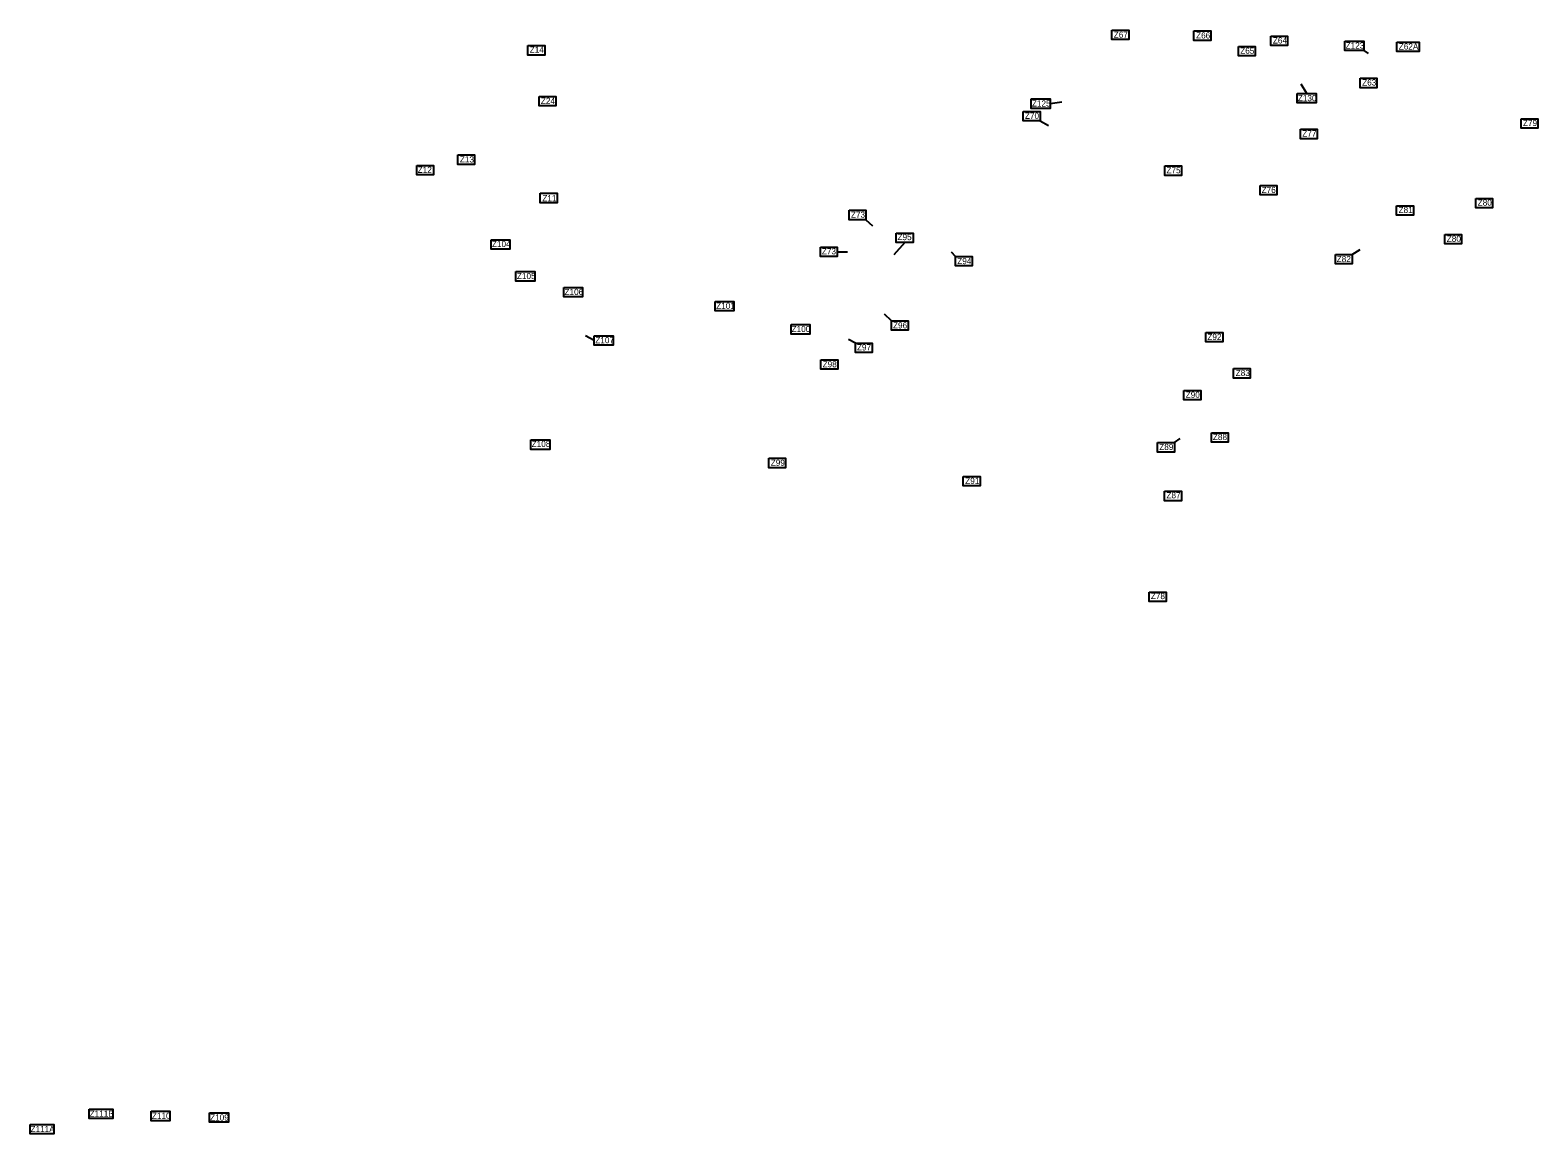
# Model space of a CAD drawing. Extents: x -443483 to -437761, y -1135258 to -1129797.
# Drawn here: x -443483 to -441026, y -1133472 to -1131673 of the extents above; entities that cross this region are included whole.
import ezdxf

# ---------------------------------------------------------------- set-up
doc = ezdxf.new("R2010")
doc.units = 0
doc.layers.add('Vrstva 3', color=7, linetype='Continuous')
doc.layers.add('Vrstva 8', color=7, linetype='Continuous')

msp = doc.modelspace()

# ---------------------------------------------------------------- linework, layer by layer
at = {"layer": 'Vrstva 3'}
for p, q in [((-441837, -1131820.4), (-441823.1, -1131827.9)), ((-442121, -1131981.6), (-442110, -1131991.6)), ((-442167.8, -1132033.9), (-442150.7, -1132034.1)), ((-442057.7, -1132018.8), (-442075.2, -1132039)), ((-441975.1, -1132041.6), (-441981.4, -1132034.6)), ((-441328.2, -1132038.3), (-441315, -1132030.3)), ((-442079.2, -1132146.3), (-442090.7, -1132135.7)), ((-442563.8, -1132178.3), (-442578.2, -1132171.1)), ((-442137.9, -1132182.9), (-442149.2, -1132176.8)), ((-441618.1, -1132344.9), (-441608.8, -1132338.2))]:
    msp.add_line(p, q, dxfattribs=at)
for points in [[(-441719.9, -1131672.7), (-441692.5, -1131672.7), (-441692.5, -1131688.1), (-441719.9, -1131688.1)], [(-441586.1, -1131673.9), (-441558.7, -1131673.9), (-441558.7, -1131689.3), (-441586.1, -1131689.3)], [(-441460.9, -1131682.5), (-441433.5, -1131682.5), (-441433.5, -1131697.9), (-441460.9, -1131697.9)], [(-441255.7, -1131692.3), (-441219.3, -1131692.3), (-441219.3, -1131707.7), (-441255.7, -1131707.7)], [(-442671.7, -1131697.8), (-442644.4, -1131697.8), (-442644.4, -1131713.2), (-442671.7, -1131713.2)], [(-441513.5, -1131699.1), (-441486.1, -1131699.1), (-441486.1, -1131714.5), (-441513.5, -1131714.5)], [(-441315.3, -1131751.1), (-441287.9, -1131751.1), (-441287.9, -1131766.5), (-441315.3, -1131766.5)], [(-442653.5, -1131780.7), (-442626.2, -1131780.7), (-442626.2, -1131796.1), (-442653.5, -1131796.1)], [(-441864.3, -1131805), (-441837, -1131805), (-441837, -1131820.4), (-441864.3, -1131820.4)], [(-441412.5, -1131834.2), (-441385.1, -1131834.2), (-441385.1, -1131849.6), (-441412.5, -1131849.6)], [(-441053, -1131817.2), (-441025.6, -1131817.2), (-441025.6, -1131832.6), (-441053, -1131832.6)], [(-442786.3, -1131876), (-442759, -1131876), (-442759, -1131891.4), (-442786.3, -1131891.4)], [(-442853.1, -1131893), (-442825.7, -1131893), (-442825.7, -1131908.4), (-442853.1, -1131908.4)], [(-441633.7, -1131893.9), (-441606.4, -1131893.9), (-441606.4, -1131909.3), (-441633.7, -1131909.3)], [(-442651.8, -1131938.6), (-442624.4, -1131938.6), (-442624.4, -1131954), (-442651.8, -1131954)], [(-441478.3, -1131925.9), (-441450.9, -1131925.9), (-441450.9, -1131941.3), (-441478.3, -1131941.3)], [(-441255.9, -1131958.8), (-441228.5, -1131958.8), (-441228.5, -1131974.2), (-441255.9, -1131974.2)], [(-441126.7, -1131946.9), (-441099.4, -1131946.9), (-441099.4, -1131962.3), (-441126.7, -1131962.3)], [(-442148.4, -1131966.2), (-442121, -1131966.2), (-442121, -1131981.6), (-442148.4, -1131981.6)], [(-442071.4, -1132003.4), (-442044, -1132003.4), (-442044, -1132018.8), (-442071.4, -1132018.8)], [(-441177.4, -1132005.6), (-441150, -1132005.6), (-441150, -1132021), (-441177.4, -1132021)], [(-442731.9, -1132014.2), (-442701.2, -1132014.2), (-442701.2, -1132029.6), (-442731.9, -1132029.6)], [(-442195.1, -1132026.2), (-442167.8, -1132026.2), (-442167.8, -1132041.6), (-442195.1, -1132041.6)], [(-441975.1, -1132041.6), (-441947.7, -1132041.6), (-441947.7, -1132057), (-441975.1, -1132057)], [(-441355.6, -1132038.3), (-441328.2, -1132038.3), (-441328.2, -1132053.7), (-441355.6, -1132053.7)], [(-442691.5, -1132066.2), (-442660.7, -1132066.2), (-442660.7, -1132081.6), (-442691.5, -1132081.6)], [(-442613.5, -1132092), (-442582.8, -1132092), (-442582.8, -1132107.4), (-442613.5, -1132107.4)], [(-442366.7, -1132114.8), (-442336, -1132114.8), (-442336, -1132130.2), (-442366.7, -1132130.2)], [(-442242.9, -1132152.5), (-442212.2, -1132152.5), (-442212.2, -1132167.9), (-442242.9, -1132167.9)], [(-442079.2, -1132146.3), (-442051.8, -1132146.3), (-442051.8, -1132161.7), (-442079.2, -1132161.7)], [(-442563.8, -1132170.6), (-442533.1, -1132170.6), (-442533.1, -1132186), (-442563.8, -1132186)], [(-442137.9, -1132182.9), (-442110.5, -1132182.9), (-442110.5, -1132198.2), (-442137.9, -1132198.2)], [(-441566.6, -1132165.3), (-441539.2, -1132165.3), (-441539.2, -1132180.7), (-441566.6, -1132180.7)], [(-442194.3, -1132209.9), (-442166.9, -1132209.9), (-442166.9, -1132225.3), (-442194.3, -1132225.3)], [(-441521.7, -1132224.2), (-441494.3, -1132224.2), (-441494.3, -1132239.6), (-441521.7, -1132239.6)], [(-441602.6, -1132259.7), (-441575.2, -1132259.7), (-441575.2, -1132275.1), (-441602.6, -1132275.1)], [(-441557.5, -1132329), (-441530.2, -1132329), (-441530.2, -1132344.4), (-441557.5, -1132344.4)], [(-442667.1, -1132340.5), (-442636.3, -1132340.5), (-442636.3, -1132355.9), (-442667.1, -1132355.9)], [(-441645.5, -1132344.9), (-441618.1, -1132344.9), (-441618.1, -1132360.3), (-441645.5, -1132360.3)], [(-442279.2, -1132370.4), (-442251.8, -1132370.4), (-442251.8, -1132385.8), (-442279.2, -1132385.8)], [(-441962.1, -1132399.9), (-441934.7, -1132399.9), (-441934.7, -1132415.3), (-441962.1, -1132415.3)], [(-441634, -1132424.2), (-441606.6, -1132424.2), (-441606.6, -1132439.6), (-441634, -1132439.6)], [(-441659, -1132588.5), (-441631.6, -1132588.5), (-441631.6, -1132603.9), (-441659, -1132603.9)], [(-443387, -1133431.3), (-443348.5, -1133431.3), (-443348.5, -1133446.7), (-443387, -1133446.7)], [(-443286.1, -1133434.8), (-443255.3, -1133434.8), (-443255.3, -1133450.2), (-443286.1, -1133450.2)], [(-443190.7, -1133437.1), (-443160, -1133437.1), (-443160, -1133452.5), (-443190.7, -1133452.5)], [(-443483.2, -1133456.1), (-443444.8, -1133456.1), (-443444.8, -1133471.5), (-443483.2, -1133471.5)], [(-443483.2, -1133456.1), (-443444.8, -1133456.1), (-443444.8, -1133471.5), (-443483.2, -1133471.5)], [(-443483.2, -1133456.1), (-443444.8, -1133456.1), (-443444.8, -1133471.5), (-443483.2, -1133471.5)]]:
    msp.add_lwpolyline(points, close=True, dxfattribs=at)
at = {"layer": 'Vrstva 8'}
for p, q in [((-441309.4, -1131706), (-441302.4, -1131710.9)), ((-441402.4, -1131775.9), (-441411.2, -1131760.6)), ((-441820.6, -1131792.4), (-441801.6, -1131789.5))]:
    msp.add_line(p, q, dxfattribs=at)
for points in [[(-441340.2, -1131690.6), (-441309.4, -1131690.6), (-441309.4, -1131706), (-441340.2, -1131706)], [(-441851.3, -1131784.7), (-441820.6, -1131784.7), (-441820.6, -1131800.1), (-441851.3, -1131800.1)], [(-441417.8, -1131775.9), (-441387.1, -1131775.9), (-441387.1, -1131791.3), (-441417.8, -1131791.3)]]:
    msp.add_lwpolyline(points, close=True, dxfattribs=at)

# ---------------------------------------------------------------- texts
at = {"layer": 'Vrstva 3'}
for s, p in [('Z67', (-441716.9, -1131685)), ('Z66', (-441582.7, -1131686.2)), ('Z64', (-441457.5, -1131694.4)), ('Z14', (-442668.9, -1131709.6)), ('Z65', (-441510.7, -1131711.2)), ('Z62A', (-441252.3, -1131704.2)), ('Z63', (-441311.9, -1131762.9)), ('Z24', (-442650.7, -1131792.9)), ('Z70', (-441861.7, -1131817.2)), ('Z77', (-441409.6, -1131846.1)), ('Z79', (-441049.9, -1131829)), ('Z13', (-442782.8, -1131888.3)), ('Z12', (-442851.5, -1131905.2)), ('Z75', (-441631, -1131906)), ('Z76', (-441475.8, -1131938.1)), ('Z11', (-442648.3, -1131951.5)), ('Z81', (-441252.6, -1131970.7)), ('Z80', (-441123.6, -1131958.7)), ('Z73', (-442145.3, -1131978.4)), ('Z95', (-442069.4, -1132014.9)), ('Z80', (-441174, -1132017.7)), ('Z104', (-442730.5, -1132026.2)), ('Z73', (-442192.7, -1132038.1)), ('Z94', (-441972, -1132054)), ('Z82', (-441353.5, -1132050.7)), ('Z105', (-442689.8, -1132078.4)), ('Z106', (-442612.2, -1132104.3)), ('Z101', (-442365, -1132127)), ('Z100', (-442242, -1132164.7)), ('Z96', (-442076.7, -1132158.8)), ('Z107', (-442562, -1132182.9)), ('Z92', (-441564.3, -1132177.6)), ('Z97', (-442135.5, -1132194.7)), ('Z98', (-442191.4, -1132222.2)), ('Z83', (-441518.1, -1132236.4)), ('Z90', (-441599.6, -1132271.8)), ('Z88', (-441555.3, -1132340.8)), ('Z108', (-442665.7, -1132352)), ('Z89', (-441642.7, -1132357)), ('Z99', (-442276, -1132382.7)), ('Z91', (-441959, -1132412.2)), ('Z87', (-441631, -1132435.7)), ('Z78', (-441656.4, -1132600)), ('Z111B', (-443386.3, -1133443.6)), ('Z110', (-443284.8, -1133447.1)), ('Z111A', (-443482.6, -1133468.7)), ('Z109', (-443189.9, -1133449.9))]:
    msp.add_text(s, height=10, dxfattribs=at).set_placement(p)
at = {"layer": 'Vrstva 8'}
for s, p in [('Z123', (-441338.9, -1131702.6)), ('Z125', (-441850.3, -1131797.1)), ('Z130', (-441416.9, -1131788.4))]:
    msp.add_text(s, height=10, dxfattribs=at).set_placement(p)

doc.saveas('drawing.dxf')
